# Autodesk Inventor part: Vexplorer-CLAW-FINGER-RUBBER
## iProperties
Created: 2007-10
Part Number: Vexplorer-CLAW-FINGER-RUBBER
Document SubType Name: Modeling
Material: Rubber
Density: 0.93 g/cm^3
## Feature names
1. Base1
